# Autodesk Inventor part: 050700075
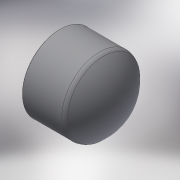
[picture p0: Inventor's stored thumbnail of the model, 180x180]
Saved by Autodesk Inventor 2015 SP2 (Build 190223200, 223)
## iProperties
Created: 2017-10
Part Number: 050700075
Material: Generic
Description: PLASSON CAP-CEMENT PVC 75
Document SubType Name: Modeling
Designer: KIM
Density: 1 g/cm^3
Appearance: Default
Author: KIM
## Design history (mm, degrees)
derived "050700.ipt"
feature "Solid1::050700.ipt"
tag "TaggingFeature1"
body "Solid1"
other parameters: "d7" = 0.75, "d9" = 88, "d28" = 1, "d29" = 44, "d30" = 75, "d31" = 67.5, "d32" = 63, "d33" = 46.2, "d34" = 7.5, "d_" = 75, "E_" = 88, "H_" = 63, "l_" = 44
